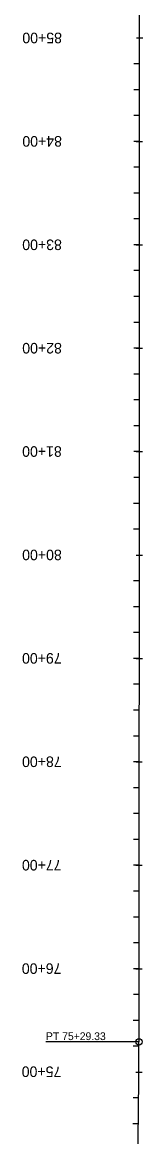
# Model space of a CAD drawing. Extents: x 11526485 to 11527255, y 9590594 to 9599170.
# Drawn here: x 11526524 to 11526640, y 9595945 to 9597022 of the extents above; entities that cross this region are included whole.
import ezdxf

# ---------------------------------------------------------------- set-up
doc = ezdxf.new("R2010")
doc.units = 0
for name, color, linetype in [('Alignment', 7, 'Continuous'), ('Default', 7, 'Continuous'), ('TextAlignment', 7, 'Continuous'), ('TextAlignmentLrg', 7, 'Continuous'), ('TextAlignmentSml', 7, 'Continuous')]:
    doc.layers.add(name, color=color, linetype=linetype)

msp = doc.modelspace()

# ---------------------------------------------------------------- linework, layer by layer
at = {"layer": 'Alignment'}
for p, q in [((11526636.9, 9596688.1), (11526637.9, 9599161)), ((11526636.5, 9596036.6), (11526636.9, 9596688.1))]:
    msp.add_line(p, q, dxfattribs=at)
msp.add_arc((11518997, 9596041.3), 7639.4, 356.46953, 359.96476, dxfattribs=at)
at = {"layer": 'Default'}
msp.add_line((11526636.5, 9596036.6), (11526636.9, 9596688.1), dxfattribs=at)
msp.add_arc((11518997, 9596041.3), 7639.4, 356.46953, 359.96476, dxfattribs=at)
at = {"layer": 'TextAlignment'}
for p in [(11526636.5, 9596036.6), (11526546.5, 9596036.7)]:
    msp.add_line(p, (11526546.5, 9596036.7), dxfattribs=at)
msp.add_circle((11526636.5, 9596036.6), 3.12, dxfattribs=at)
at = {"layer": 'TextAlignmentLrg'}
for p, q in [((11526634, 9597007.3), (11526640.1, 9597007.3)), ((11526637, 9596907.3), (11526631.5, 9596907.3)), ((11526636.9, 9596807.3), (11526631.5, 9596807.3)), ((11526636.9, 9596707.3), (11526631.4, 9596707.3)), ((11526636.8, 9596607.3), (11526631.4, 9596607.3)), ((11526633.7, 9596507.3), (11526639.8, 9596507.3)), ((11526636.7, 9596407.3), (11526631.3, 9596407.3)), ((11526636.7, 9596307.3), (11526631.2, 9596307.3)), ((11526636.6, 9596207.3), (11526631.1, 9596207.3)), ((11526636.5, 9596107.3), (11526631.1, 9596107.3)), ((11526633.4, 9596007.3), (11526639.5, 9596007.3))]:
    msp.add_line(p, q, dxfattribs=at)
at = {"layer": 'TextAlignmentSml'}
for p, q in [((11526634, 9597007.3), (11526640.1, 9597007.3)), ((11526637, 9596982.3), (11526631.6, 9596982.3)), ((11526637, 9596957.3), (11526631.5, 9596957.3)), ((11526637, 9596932.3), (11526631.5, 9596932.3)), ((11526633.9, 9596907.3), (11526640, 9596907.3)), ((11526637, 9596882.3), (11526631.5, 9596882.3)), ((11526637, 9596857.3), (11526631.5, 9596857.3)), ((11526636.9, 9596832.3), (11526631.5, 9596832.3)), ((11526633.9, 9596807.3), (11526640, 9596807.3)), ((11526636.9, 9596782.3), (11526631.5, 9596782.3)), ((11526636.9, 9596757.3), (11526631.5, 9596757.3)), ((11526636.9, 9596732.3), (11526631.4, 9596732.3)), ((11526633.8, 9596707.3), (11526640, 9596707.3)), ((11526636.9, 9596682.3), (11526631.4, 9596682.3)), ((11526636.9, 9596657.3), (11526631.4, 9596657.3)), ((11526636.9, 9596632.3), (11526631.4, 9596632.3)), ((11526633.8, 9596607.3), (11526639.9, 9596607.3)), ((11526636.8, 9596582.3), (11526631.4, 9596582.3)), ((11526636.8, 9596557.3), (11526631.3, 9596557.3)), ((11526636.8, 9596532.3), (11526631.3, 9596532.3)), ((11526633.7, 9596507.3), (11526639.8, 9596507.3)), ((11526636.8, 9596482.3), (11526631.3, 9596482.3)), ((11526636.7, 9596457.3), (11526631.3, 9596457.3)), ((11526636.7, 9596432.3), (11526631.3, 9596432.3)), ((11526633.7, 9596407.3), (11526639.8, 9596407.3)), ((11526636.7, 9596382.3), (11526631.2, 9596382.3)), ((11526636.7, 9596357.3), (11526631.2, 9596357.3)), ((11526636.7, 9596332.3), (11526631.2, 9596332.3)), ((11526633.6, 9596307.3), (11526639.7, 9596307.3)), ((11526636.6, 9596282.3), (11526631.2, 9596282.3)), ((11526636.6, 9596257.3), (11526631.2, 9596257.3)), ((11526636.6, 9596232.3), (11526631.1, 9596232.3)), ((11526633.5, 9596207.3), (11526639.7, 9596207.3)), ((11526636.6, 9596182.3), (11526631.1, 9596182.3)), ((11526636.6, 9596157.3), (11526631.1, 9596157.3)), ((11526636.5, 9596132.3), (11526631.1, 9596132.3)), ((11526633.5, 9596107.3), (11526639.6, 9596107.3)), ((11526636.5, 9596082.3), (11526631.1, 9596082.3)), ((11526636.5, 9596057.3), (11526631, 9596057.3)), ((11526636.5, 9596032.3), (11526631, 9596032.3)), ((11526633.4, 9596007.3), (11526639.5, 9596007.3)), ((11526636.3, 9595982.3), (11526630.8, 9595982.4)), ((11526636, 9595957.3), (11526630.6, 9595957.4))]:
    msp.add_line(p, q, dxfattribs=at)

# ---------------------------------------------------------------- texts
at = {"layer": 'TextAlignment'}
for s, p in [('PT', (11526546.5, 9596038.3)), ('75+29.33', (11526562.2, 9596038.3))]:
    msp.add_text(s, height=7.5, rotation=359.9648, dxfattribs=at).set_placement(p)
at = {"layer": 'TextAlignmentLrg'}
for s, rotation, p in [('85+00', 179.9754, (11526562, 9597012.4)), ('80+00', 179.9648, (11526561.8, 9596512.5)), ('75+00', 179.7448, (11526561.4, 9596012.7))]:
    msp.add_text(s, height=10.2, rotation=rotation, dxfattribs=at).set_placement(p)
at = {"layer": 'TextAlignmentSml'}
for s, rotation, p in [('85+00', 179.9754, (11526562, 9597012.4)), ('84+00', 179.9754, (11526562, 9596912.4)), ('83+00', 179.9754, (11526561.9, 9596812.4)), ('82+00', 179.9754, (11526561.9, 9596712.4)), ('81+00', 179.9648, (11526561.8, 9596612.5)), ('80+00', 179.9648, (11526561.8, 9596512.5)), ('79+00', 179.9648, (11526561.7, 9596412.5)), ('78+00', 179.9648, (11526561.7, 9596312.5)), ('77+00', 179.9648, (11526561.6, 9596212.5)), ('76+00', 179.9648, (11526561.5, 9596112.5)), ('75+00', 179.7448, (11526561.4, 9596012.7))]:
    msp.add_text(s, height=10.2, rotation=rotation, dxfattribs=at).set_placement(p)

doc.saveas('drawing.dxf')
